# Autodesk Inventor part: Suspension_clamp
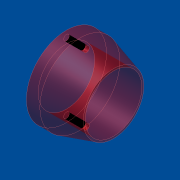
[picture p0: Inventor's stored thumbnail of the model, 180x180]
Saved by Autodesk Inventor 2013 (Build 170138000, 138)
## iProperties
Shininess: 20.0
Length Units: 11269
Angle Units: 11279
Time Units: 11290
Mass Units: 11283
Length Display Precision: 3
Angle Display Precision: 2
Created: 2001-04
Part Number: Suspension_clamp
Material: Standard
Document SubType Name: Modellieren
Designer: dl
Density: 1 g/cm^3
Density: 0.0
Volumn: 0.0
Area: 0.0
PropertySet Name: Model Information
Control State: 0
Master: False
Checked Out: False
Author: dl
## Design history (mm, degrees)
body "Solid1"
sketch "Sketch2"
  geometry: C1 r 22.5 at (0, 0) reference; 1 further point
  constraints: 1 coincident
sketch "Sketch3"
  geometry: C1 r 29.75 at (0, 0) reference; 1 further point
  dimensions: "d14" = 0 horizontal distance of C1.centre point (0, 25); "d15" = 25 distance of C1.centre point (0, 25)
revolve "Revolution1" stored, may be unused: angle "d6" = 90 deg
hole "Hole1" sketch "Sketch2" diameter "d7" = 42.05; stored, may be unused: countersink angle "d11" = 60 deg, drill point angle "d13" = 118 deg; dims "d8" = 6, "d9" = 4, "d10" = 2, "d12" = 8
hole "Hole2" sketch "Sketch3" diameter "d16" = 4.134; stored, may be unused: countersink angle "d20" = 60 deg, drill point angle "d22" = 118 deg; dims "d17" = 12, "d18" = 4, "d19" = 2, "d21" = 15
pattern_circular "Circular Pattern1" dims angle "d25" = 360 deg
sketch "Sketch1"
  geometry: L1 (0.885, 0.033)-(0.885, 29.783); L2 (0.885, 29.783)-(10.885, 29.783); L3 (10.885, 29.783)-(35.885, 22.533); L4 (35.885, 22.533)-(35.885, 0.033); L5 (35.885, 0.033)-(0.885, 0.033)
  constraints: 10 end point, 2 perpendicular, 1 horizontal, 1 vertical
  dimensions: "d0" = 29.75 distance of L1.start L1.end; "d1" = 22.5 distance of L3.end L4.end; "d4" = 35 distance of L4.end L1.start; "d5" = 10 distance of L1.end L2.end
